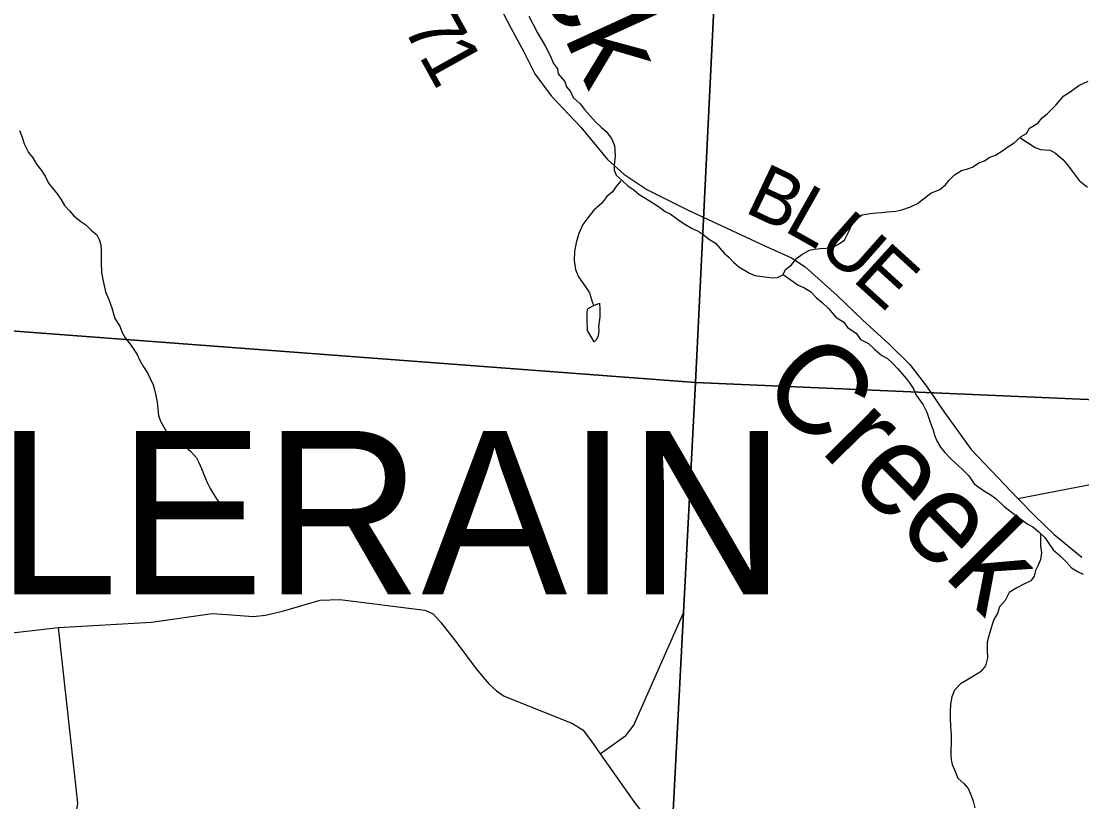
# Model space of a CAD drawing. Extents: x 0 to 34, y 0 to 22.
# Drawn here: x 6.66 to 7.766, y 18.576 to 19.391 of the extents above; entities that cross this region are included whole.
import ezdxf

# ---------------------------------------------------------------- set-up
doc = ezdxf.new("R2010")
doc.units = 0
for name, color, linetype in [('GM_X_County_Road', 7, 'Continuous'), ('GM_X_County_Road_Text', 7, 'Continuous'), ('GM_X_Minor_Lake', 7, 'Continuous'), ('GM_X_Minor_River', 7, 'Continuous'), ('GM_X_Minor_River_Text', 7, 'Continuous'), ('GM_X_Section', 7, 'Continuous'), ('GM_X_Township_Road', 7, 'Continuous'), ('GM_X_Township_Text', 7, 'Continuous')]:
    doc.layers.add(name, color=color, linetype=linetype)

msp = doc.modelspace()

# ---------------------------------------------------------------- linework, layer by layer
at = {"layer": 'GM_X_County_Road'}
for points in [[(7.1506, 19.4223), (7.1704, 19.384), (7.1838, 19.359), (7.1954, 19.336), (7.2124, 19.313), (7.2434, 19.2803), (7.2711, 19.2467), (7.2883, 19.2311), (7.3122, 19.2151), (7.3555, 19.1936), (7.436, 19.156), (7.4632, 19.1438), (7.4775, 19.1345), (7.511, 19.1045), (7.5373, 19.0794), (7.5652, 19.0539), (7.5865, 19.0326), (7.604, 19.0101), (7.6229, 18.9825), (7.6507, 18.944), (7.6994, 18.893), (7.7169, 18.8749), (7.7372, 18.8554), (7.7661, 18.8318)], [(6.6985, 18.7581), (6.7956, 18.7637), (6.8589, 18.773), (6.8789, 18.7716), (6.9016, 18.7697), (6.9146, 18.7712), (6.9321, 18.7752), (6.9716, 18.7869), (6.992, 18.7873), (7.0808, 18.7765), (7.0894, 18.7724), (7.0978, 18.7631), (7.1142, 18.7424), (7.1341, 18.7152), (7.1473, 18.6996), (7.1554, 18.6921), (7.1635, 18.6865), (7.2339, 18.6584), (7.2454, 18.6516), (7.2541, 18.6399), (7.2636, 18.6264), (7.3012, 18.5731), (7.3335, 18.5347)], [(6.2132, 17.9528), (6.2484, 17.9805), (6.2767, 18.0015), (6.2948, 18.0127), (6.3396, 18.0389), (6.3826, 18.0567), (6.4553, 18.094), (6.4873, 18.1117), (6.5294, 18.1364), (6.5622, 18.1557), (6.5835, 18.1719), (6.6046, 18.1941), (6.6487, 18.2393), (6.656, 18.2562), (6.6633, 18.2742), (6.6678, 18.2988), (6.6717, 18.3443), (6.6757, 18.3651), (6.6809, 18.3881), (6.7005, 18.467), (6.7138, 18.5392), (6.7158, 18.5574), (6.7186, 18.5748), (6.6985, 18.7581)], [(6.4295, 18.7441), (6.4922, 18.7381), (6.518, 18.7378), (6.5599, 18.7408), (6.6345, 18.751), (6.6985, 18.7581)]]:
    msp.add_lwpolyline(points, dxfattribs=at)
at = {"layer": 'GM_X_Minor_Lake'}
for points in [[(7.257, 19.0944), (7.2629, 19.0965), (7.2631, 19.09), (7.2633, 19.0824), (7.2619, 19.0718), (7.2621, 19.068), (7.2616, 19.0627), (7.2596, 19.0586), (7.2573, 19.0564), (7.2504, 19.068), (7.2499, 19.0798), (7.2501, 19.0877), (7.2506, 19.0908)], [(7.257, 19.0944), (7.2506, 19.0908)]]:
    msp.add_lwpolyline(points, dxfattribs=at)
at = {"layer": 'GM_X_Minor_River'}
for points in [[(7.1893, 19.3961), (7.1933, 19.3883), (7.1982, 19.3786), (7.2061, 19.3651), (7.2111, 19.3558), (7.215, 19.3469), (7.219, 19.3411), (7.2199, 19.3361), (7.2269, 19.3279), (7.2286, 19.3225), (7.2326, 19.3174), (7.2354, 19.3112), (7.2428, 19.3045), (7.2471, 19.2987), (7.253, 19.292), (7.2588, 19.2857), (7.2647, 19.2802), (7.2699, 19.2758), (7.2753, 19.2684), (7.2785, 19.2611), (7.279, 19.2558), (7.2792, 19.25), (7.2781, 19.241), (7.2783, 19.2356), (7.2804, 19.2302), (7.2867, 19.2247), (7.2926, 19.2192), (7.2989, 19.2144), (7.3044, 19.21), (7.3096, 19.2068), (7.3159, 19.2032), (7.3245, 19.1975), (7.3315, 19.1924), (7.3367, 19.1899), (7.3419, 19.1859), (7.3501, 19.1803), (7.3594, 19.1747), (7.3657, 19.1718), (7.3709, 19.1682), (7.3776, 19.163), (7.3839, 19.1594), (7.3883, 19.1539), (7.393, 19.1488), (7.3978, 19.1448), (7.4026, 19.1394), (7.4081, 19.1346), (7.4193, 19.1281), (7.4249, 19.1257), (7.4377, 19.1237), (7.4438, 19.1231), (7.4487, 19.1233), (7.4541, 19.1262), (7.4574, 19.1321), (7.4632, 19.1365), (7.4688, 19.1435), (7.4739, 19.1475), (7.482, 19.1518), (7.4873, 19.1531), (7.493, 19.1537), (7.4995, 19.1539), (7.5052, 19.1544), (7.5114, 19.158), (7.5184, 19.1623), (7.5233, 19.172), (7.5258, 19.178), (7.529, 19.1832), (7.5368, 19.1887)], [(7.5368, 19.1887), (7.5452, 19.1903), (7.5517, 19.1908), (7.557, 19.1914), (7.5635, 19.1919), (7.5722, 19.1928), (7.5783, 19.1941), (7.5872, 19.1972), (7.5945, 19.2007), (7.6086, 19.2113), (7.6178, 19.2151), (7.6237, 19.2202), (7.6276, 19.225), (7.6331, 19.2306), (7.6405, 19.2352), (7.6459, 19.2366), (7.652, 19.2386), (7.6586, 19.243), (7.6644, 19.2451), (7.6695, 19.2487), (7.676, 19.2511), (7.6826, 19.2554), (7.688, 19.2591), (7.6954, 19.2641), (7.7029, 19.2707), (7.7083, 19.2736), (7.7115, 19.2792), (7.7201, 19.2846), (7.7248, 19.2901), (7.7303, 19.2945), (7.7389, 19.3033), (7.7472, 19.3129), (7.7538, 19.3172), (7.7628, 19.3237), (7.7728, 19.3283)], [(6.6579, 19.2769), (6.6607, 19.27), (6.6627, 19.263), (6.6673, 19.2538), (6.6717, 19.2483), (6.6756, 19.2417), (6.6807, 19.2351), (6.6847, 19.2292), (6.6882, 19.2219), (6.697, 19.2109), (6.701, 19.2051), (6.7049, 19.1985), (6.71, 19.193), (6.7144, 19.1879), (6.7218, 19.182), (6.727, 19.1784), (6.7325, 19.1728), (6.7384, 19.1681), (6.7409, 19.163), (6.7426, 19.1577), (6.7431, 19.1516), (6.7431, 19.1394), (6.7435, 19.1288), (6.7448, 19.1215), (6.7477, 19.1085), (6.7509, 19.1004), (6.754, 19.0919), (6.7574, 19.0808), (6.7624, 19.0726), (6.7645, 19.0668), (6.7681, 19.0606), (6.7743, 19.0524), (6.7804, 19.0431), (6.7829, 19.0377), (6.7872, 19.0303), (6.7915, 19.0241), (6.7943, 19.0179), (6.7971, 19.0114), (6.7985, 19.0064), (6.8002, 19.0002), (6.8015, 18.9933), (6.802, 18.9865), (6.8029, 18.9796), (6.8049, 18.9735), (6.8107, 18.963), (6.8143, 18.9576), (6.8209, 18.9524), (6.8277, 18.9495), (6.8361, 18.9424), (6.8424, 18.9353), (6.8448, 18.9303), (6.8477, 18.9241), (6.8508, 18.916), (6.8536, 18.9094), (6.8568, 18.9033), (6.8597, 18.8982), (6.8633, 18.8924), (6.8691, 18.8842), (6.873, 18.8788), (6.8767, 18.8737)], [(7.7015, 19.2695), (7.7173, 19.2592), (7.7229, 19.2571), (7.7278, 19.2565), (7.7331, 19.2564), (7.7387, 19.2531), (7.7461, 19.2464), (7.7512, 19.2409), (7.7559, 19.2343), (7.7632, 19.2245), (7.772, 19.2178)], [(7.2852, 19.2244), (7.28, 19.2181), (7.2764, 19.2129), (7.2705, 19.2078), (7.2654, 19.2011), (7.2571, 19.1938), (7.2508, 19.1857), (7.2456, 19.1786), (7.2415, 19.1693), (7.2385, 19.1595), (7.2367, 19.1508), (7.2363, 19.1413), (7.2379, 19.1318), (7.2411, 19.1241), (7.245, 19.1182), (7.249, 19.1128), (7.2526, 19.1073), (7.2557, 19.0969), (7.257, 19.0944)], [(7.4544, 19.1266), (7.4701, 19.1154), (7.4761, 19.1129), (7.4835, 19.1084), (7.4894, 19.1021), (7.4953, 19.0974), (7.5019, 19.0911), (7.5096, 19.0821), (7.5177, 19.0768), (7.5217, 19.0714), (7.5306, 19.0654), (7.5353, 19.0587), (7.5435, 19.0547), (7.5502, 19.0484), (7.5575, 19.042), (7.5635, 19.0388), (7.569, 19.0336), (7.5738, 19.0285), (7.5785, 19.023), (7.5829, 19.018), (7.5869, 19.0125), (7.5905, 19.0074), (7.5933, 19.0005), (7.6006, 18.9907), (7.6045, 18.983), (7.6079, 18.9726), (7.611, 18.9642), (7.6127, 18.958), (7.6152, 18.9522), (7.6188, 18.9464), (7.6231, 18.9409), (7.6297, 18.9339), (7.6411, 18.9236), (7.6481, 18.9165), (7.6539, 18.9083), (7.6635, 18.9011), (7.6706, 18.8971), (7.6765, 18.8927), (7.6846, 18.8848), (7.6942, 18.8777), (7.7023, 18.8713), (7.7098, 18.8661), (7.715, 18.8633), (7.7213, 18.8581), (7.7275, 18.8522), (7.7315, 18.846), (7.7362, 18.8393), (7.7435, 18.833), (7.7498, 18.8267), (7.7553, 18.8204), (7.7623, 18.8164), (7.7676, 18.8139)], [(7.723, 18.8565), (7.723, 18.8432), (7.7239, 18.836), (7.7229, 18.8292), (7.7204, 18.8232), (7.7176, 18.8176), (7.7162, 18.8119), (7.713, 18.8071), (7.7057, 18.8035), (7.6983, 18.7996), (7.6902, 18.7949), (7.6861, 18.7863), (7.6802, 18.7797), (7.6781, 18.7729), (7.6745, 18.7674), (7.6727, 18.7613), (7.6689, 18.7497), (7.6672, 18.7429), (7.6672, 18.7346), (7.6677, 18.7266), (7.6655, 18.7183), (7.6604, 18.712), (7.653, 18.7073), (7.646, 18.7034), (7.6395, 18.6994), (7.6332, 18.6928), (7.6303, 18.686), (7.6292, 18.6781), (7.6286, 18.6701), (7.6288, 18.6644), (7.6292, 18.6542), (7.6297, 18.6473), (7.6299, 18.642), (7.6293, 18.6257), (7.6299, 18.6203), (7.6309, 18.6153), (7.6337, 18.6092), (7.6368, 18.6011), (7.6434, 18.5951), (7.6474, 18.5901), (7.6506, 18.5831), (7.6527, 18.577), (7.6543, 18.5701)]]:
    msp.add_lwpolyline(points, dxfattribs=at)
at = {"layer": 'GM_X_Section'}
for points in [[(6.6475, 20.0689), (7.4124, 20.0219), (7.3629, 19.0139), (6.5612, 19.0743)], [(7.4124, 20.0219), (8.6611, 20.0077), (8.567, 18.9616), (7.3629, 19.0139)], [(6.5612, 19.0743), (7.3629, 19.0139), (7.3111, 18.02), (6.4651, 18.0799)], [(8.567, 18.9616), (8.4694, 17.9573), (7.3111, 18.02), (7.3629, 19.0139)]]:
    msp.add_lwpolyline(points, close=True, dxfattribs=at)
at = {"layer": 'GM_X_Township_Road'}
msp.add_line((7.6994, 18.893), (7.9175, 18.9346), dxfattribs=at)
msp.add_lwpolyline([(7.2636, 18.6264), (7.2903, 18.6456), (7.2943, 18.6504), (7.2986, 18.6563), (7.3506, 18.7735)], dxfattribs=at)

# ---------------------------------------------------------------- texts
at = {"layer": 'GM_X_County_Road_Text'}
for s, rotation, p in [('7', 298.9821, (7.057, 19.3853)), ('1', 299.0289, (7.0738, 19.3549)), ('B', 334.6337, (7.4127, 19.1924)), ('L', 330.6006, (7.4539, 19.1729)), ('U', 318.5207, (7.4883, 19.1539)), ('E', 317.7102, (7.5256, 19.1209))]:
    msp.add_text(s, height=0.0568, rotation=rotation, dxfattribs=at).set_placement(p)
at = {"layer": 'GM_X_Minor_River_Text'}
for s, rotation, p in [('Rock', 294.5569, (7.1316, 19.5798)), ('Creek', 314.7329, (7.4275, 19.0075))]:
    msp.add_text(s, height=0.0947, rotation=rotation, dxfattribs=at).set_placement(p)
at = {"layer": 'GM_X_Township_Text'}
msp.add_text('COLERAIN', height=0.17045, rotation=0, dxfattribs=at).set_placement((6.2919, 18.793))

doc.saveas('drawing.dxf')
